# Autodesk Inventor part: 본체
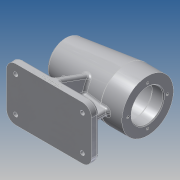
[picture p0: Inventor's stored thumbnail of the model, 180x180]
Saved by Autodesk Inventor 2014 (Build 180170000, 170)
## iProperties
Created: 2018-09
Part Number: 본체
Material: 알루미늄 6061
Document SubType Name: Modeling
Designer: kb542
Density: 2.71 g/cm^3
Appearance: 알루미늄 - 평지
Mass: 737.08 g
Surface Area: 664.757 cm^2
Volume: 271.985 cm^3
Author: kb542
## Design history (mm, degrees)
sketch "스케치2"
  geometry: L1 (-56, -35)-(56, -35); L2 (56, -35)-(56, 35); L3 (56, 35)-(-56, 35); L4 (-56, 35)-(-56, -35); L5 (-56, -35)-(56, 35); L6 (56, -35)-(-56, 35); 3 further points
  constraints: 12 end point, 3 midpoint, 2 parallel, 1 coincident, 1 horizontal, 1 perpendicular
  dimensions: "d0" = 112 distance of L2.end L3.end; "d1" = 70 distance between parallel lines of L1 L3
extrude "돌출1" new body sketch "스케치2" distance "d2" = 10; taper "d3" = 0 deg
sketch "스케치5"
  geometry: L1 (-52.27, 98.144)-(28, 108); L2 (28, 108)-(56, 108); L3 (56, 108)-(56, 74); L4 (56, 74)-(-56, 74); L5 (56, 0)-(56, 10) reference; L6 (-56, 0)-(56, 0) reference; A1 r 80 centre (24, 74) between (-52.27, 98.144) and (-56, 74); 1 further point
  constraints: 8 end point, 2 perpendicular, 2 point on circle, 1 centre point, 1 horizontal, 1 point on line
  dimensions: "d4" = 0 distance between parallel lines of L3 L5; "d5" = 28 distance of L1.end L2.end; "d6" = 112 distance from line of L3 L4.end; "d7" = 7 deg angle of L2 L1; "d8" = 80 radius of A1; "d9" = 68 diameter of L2 L4; "d10" = 74 distance between parallel lines of L4 L6
revolve "회전1" sketch "스케치5" stored, may be unused: angle "d11" = 90 deg
sketch "스케치6"
  geometry: L1 (-38, 10)-(-27.436, 49.426); L2 (38, 43.205)-(38, 10); L3 (56, 10)-(-56, 10) reference; L4 (56, 0)-(56, 10) reference; L5 (-56, 0)-(-56, 10) reference; L6 (-56, 10)-(56, 10) reference; L7 (-38, 10)-(38, 10); L8 (-27.436, 49.426)-(38, 43.205); 2 further points
  constraints: 8 end point, 2 point on line, 1 collinear, 1 vertical
  dimensions: "d12" = 18 distance between parallel lines of L4 L2; "d13" = 18 distance from line of L1.start L5; "d14" = 105 deg angle of L1 L3
extrude "돌출2" join sketch "스케치6" stored distance "d15" = 8; taper "d16" = 0 deg
sketch "스케치7"
  geometry: L1 (10, -35)-(0, -35) reference; L2 (0, -35)-(0, 35) reference; L3 (0, 35)-(10, 35) reference; L4 (10, 35)-(10, 4) reference; L5 (10, 4)-(43.701, 4) reference; L6 (43.701, -4)-(10, -4) reference; L7 (10, -4)-(10, -35) reference; L8 (10, 35)-(56.666, 18.015); L9 (10, -35)-(56.666, -18.015); L10 (10, 35)-(10, -35); L11 (10, -35)-(10, 35) reference; L12 (10, -35)-(0, -35) reference; L13 (0, -35)-(0, 35) reference; L14 (0, 35)-(10, 35) reference; L15 (10, 35)-(10, 4) reference; L16 (10, 4)-(43.701, 4) reference; L17 (43.701, -4)-(10, -4) reference; L18 (10, -4)-(10, -35) reference; A1 r 30.562 centre (74, 0) between (43.701, -4) and (43.701, 4) reference; A2 r 30.562 centre (74, 0) between (43.701, -4) and (43.701, 4) reference; A3 r 25 centre (74, 0) between (56.666, 18.015) and (56.666, -18.015); 4 further points
  constraints: 6 end point, 4 point on circle, 2 point on line, 1 centre point, 1 coincident, 1 collinear
  dimensions: "d17" = 110 deg angle of L8 L10; "d18" = 110 deg angle of L9 L7; "d21" = 50 diameter of A3
extrude "돌출5" join sketch "스케치7" stored distance "d24" = 8; taper "d25" = 0 deg
sketch "스케치8"
  geometry: L1 (-56, 74)-(76.223, 74); L2 (-50, 74)-(-50, 84.5); L3 (-50, 84.5)-(-47, 84.5); L4 (-43, 91.5)-(-25, 91.5); L5 (-25, 91.5)-(-25, 95); L6 (-25, 95)-(-13, 95); L7 (-13, 95)-(-13, 98); L8 (-13, 98)-(41, 98); L9 (41, 98)-(41, 95); L10 (41, 95)-(56, 95); L11 (56, 95)-(56, 74); L12 (-43, 91.5)-(-43, 90); L13 (-43, 90)-(-47, 90); L14 (-47, 90)-(-47, 84.5); L15 (56, 0)-(-56, 0) reference; L16 (56, 0)-(56, 10) reference; L17 (56, 40)-(56, 108) reference; 2 further points
  constraints: 28 end point, 9 parallel, 3 perpendicular, 3 point on line, 1 horizontal, 1 midpoint
  dimensions: "d28" = 42 diameter of L10 L1; "d29" = 48 diameter of L8 L1; "d31" = 54 distance between parallel lines of L9 L7; "d32" = 42 diameter of L6 L1; "d33" = 12 distance between parallel lines of L7 L5; "d37" = 3 distance between parallel lines of L14 L2; "d38" = 21 diameter of L3 L1; "d39" = 32 diameter of L13 L1; "d40" = 35 diameter of L4 L1; "d41" = 4 distance between parallel lines of L12 L14; "d42" = 18 distance of L4.start L4.end; "d45" = 0 distance between parallel lines of L16 L11; "d46" = 15 distance of L9.end L10.end
revolve "회전2" sketch "스케치8" stored, may be unused: angle "d47" = 90 deg
sketch "스케치9" dims "d48" = 52
  geometry: C1 r 34 at (0, 0) reference; 3 further points
  constraints: 1 coincident, 1 vertical alignment, 2 other
hole "구멍1" sketch "스케치9" at (0, 26) diameter "d49" = 3.242; stored, may be unused: countersink angle "d53" = 90 deg, drill point angle "d55" = 118 deg; dims "d50" = 8, "d51" = 4, "d52" = 2, "d54" = 11
fillet "모깎기1" dims "d59" = 12
hole "구멍2" diameter "d62" = 5.5; stored, may be unused: countersink angle "d66" = 90 deg, drill point angle "d68" = 118 deg; dims "d60" = 10, "d61" = 10, "d63" = 8, "d64" = 9.5, "d65" = 5.4, "d67" = 11
fillet "모깎기2" dims "d69" = 3
fillet "모깎기3" dims "d70" = 3
fillet "모깎기4" dims "d71" = 3
fillet "모깎기5" dims "d72" = 3
fillet "모깎기6" dims "d73" = 3
fillet "모깎기7" dims "d74" = 0.3
fillet "모깎기8" dims "d75" = 3
fillet "모깎기9" dims "d76" = 3
chamfer "모따기1" distance "d77" = 1; stored, may be unused: second distance "d78" = 2, angle "d79" = 45 deg
sketch "스케치10"
  geometry: L1 (0, 0)-(88, 0) reference; L2 (100, 0)-(100, 7) reference; 2 further points
  constraints: 1 other
  dimensions: "d80" = 56 distance from line of point (44, 3) L2; "d81" = 3 distance from line of L1 point (44, 3)
feature "엠보싱1" sketch "스케치10" dims "d0" = 112, "d1" = 70, "d82" = 0.5, "d83" = 0
fillet "모깎기10" dims "d84" = 3
node "솔리드1"
pattern_circular "원형 패턴1" dims angle "d57" = 360 deg
mirror "대칭1"
mirror "대칭2"
node "절단 모서리 투영1"
node "절단 모서리 투영2"
